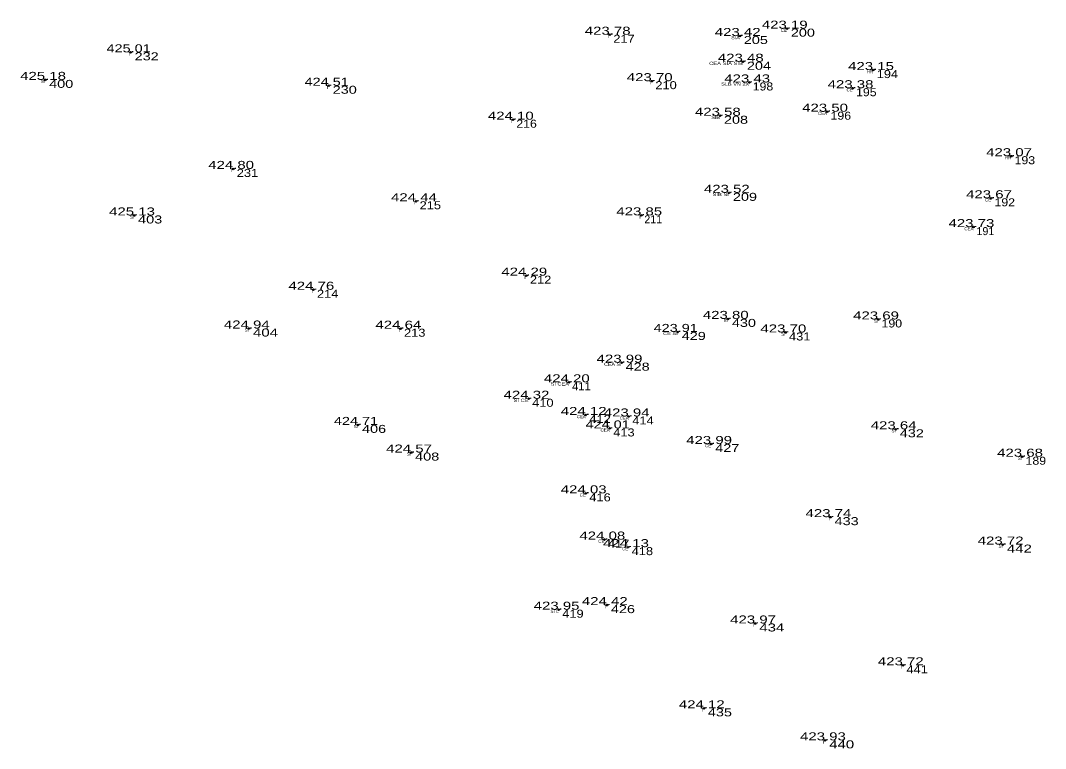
# Model space of a CAD drawing. Extents: x -639373 to -639056, y -1138651 to -1138359.
# Drawn here: x -639278.4 to -639182.3, y -1138568.9 to -1138500.7 of the extents above; entities that cross this region are included whole.
import ezdxf
from ezdxf.enums import TextEntityAlignment as Align

# ---------------------------------------------------------------- set-up
doc = ezdxf.new("R2010")
doc.units = 0
doc.header["$LTSCALE"] = 0.3
doc.header["$PDMODE"] = 32
doc.header["$PDSIZE"] = 0.15
for name, color, linetype in [('11', 7, 'Continuous'), ('13', 7, 'Continuous'), ('14', 7, 'Continuous'), ('57', 7, 'Continuous')]:
    doc.layers.add(name, color=color, linetype=linetype)

msp = doc.modelspace()

# ---------------------------------------------------------------- linework, layer by layer
at = {"layer": '11'}
for p in [(-639223.19, -1138502.05), (-639211, -1138502.17), (-639206.59, -1138501.48), (-639268.11, -1138503.7), (-639210.71, -1138504.58), (-639198.5, -1138505.36), (-639276.12, -1138506.28), (-639249.54, -1138506.83), (-639219.25, -1138506.4), (-639210.11, -1138506.52), (-639200.42, -1138507.06), (-639232.27, -1138510.01), (-639212.86, -1138509.64), (-639202.81, -1138509.26), (-639185.56, -1138513.43), (-639258.49, -1138514.62), (-639241.35, -1138517.65), (-639212.02, -1138516.86), (-639187.44, -1138517.37), (-639267.78, -1138518.98), (-639220.23, -1138518.97), (-639189.09, -1138520.07), (-639231.01, -1138524.62), (-639250.97, -1138525.94), (-639212.12, -1138528.67), (-639198.03, -1138528.72), (-639257.02, -1138529.57), (-639242.81, -1138529.59), (-639216.82, -1138529.89), (-639206.72, -1138529.94), (-639222.08, -1138532.77), (-639227.02, -1138534.61), (-639230.8, -1138536.15), (-639225.44, -1138537.67), (-639221.41, -1138537.81), (-639246.79, -1138538.6), (-639223.2, -1138538.93), (-639196.38, -1138539.01), (-639213.68, -1138540.39), (-639241.81, -1138541.19), (-639184.53, -1138541.58), (-639225.44, -1138545.01), (-639202.49, -1138547.24), (-639223.69, -1138549.34), (-639221.47, -1138550.05), (-639186.35, -1138549.81), (-639227.98, -1138555.91), (-639223.46, -1138555.48), (-639209.56, -1138557.2), (-639195.71, -1138561.12), (-639214.37, -1138565.15), (-639203.01, -1138568.15)]:
    msp.add_point(p, dxfattribs=at)

# ---------------------------------------------------------------- texts
at = {"layer": '13'}
for s, width, p in [(' 217', 1.2, (-639223.19, -1138502.8)), (' 205', 1.35, (-639211, -1138502.92)), (' 200', 1.35, (-639206.59, -1138502.23)), (' 232', 1.35, (-639268.11, -1138504.45)), (' 204', 1.35, (-639210.71, -1138505.33)), (' 194', 1.2, (-639198.5, -1138506.11)), (' 400', 1.35, (-639276.12, -1138507.03)), (' 230', 1.35, (-639249.54, -1138507.58)), (' 210', 1.2, (-639219.25, -1138507.15)), (' 198', 1.15, (-639210.11, -1138507.27)), (' 195', 1.15, (-639200.42, -1138507.81)), (' 216', 1.15, (-639232.27, -1138510.76)), (' 208', 1.35, (-639212.86, -1138510.39)), (' 196', 1.15, (-639202.81, -1138510.01)), (' 193', 1.15, (-639185.56, -1138514.18)), (' 231', 1.2, (-639258.49, -1138515.37)), (' 215', 1.2, (-639241.35, -1138518.4)), (' 209', 1.35, (-639212.02, -1138517.61)), (' 192', 1.15, (-639187.44, -1138518.12)), (' 403', 1.35, (-639267.78, -1138519.73)), (' 212', 1.2, (-639231.01, -1138525.37)), (' 214', 1.2, (-639250.97, -1138526.69)), (' 430', 1.35, (-639212.12, -1138529.42)), (' 190', 1.15, (-639198.03, -1138529.47)), (' 404', 1.4, (-639257.02, -1138530.32)), (' 213', 1.2, (-639242.81, -1138530.34)), (' 429', 1.35, (-639216.82, -1138530.64)), (' 431', 1.2, (-639206.72, -1138530.69)), (' 428', 1.35, (-639222.08, -1138533.52)), (' 411', 1.05, (-639227.02, -1138535.36)), (' 410', 1.2, (-639230.8, -1138536.9)), (' 412', 1.2, (-639225.44, -1138538.42)), (' 414', 1.2, (-639221.41, -1138538.56)), (' 406', 1.35, (-639246.79, -1138539.35)), (' 413', 1.2, (-639223.2, -1138539.68)), (' 432', 1.35, (-639196.38, -1138539.76)), (' 427', 1.35, (-639213.68, -1138541.14)), (' 408', 1.35, (-639241.81, -1138541.94)), (' 189', 1.15, (-639184.53, -1138542.33)), (' 416', 1.2, (-639225.44, -1138545.76)), (' 433', 1.35, (-639202.49, -1138547.99)), (' 417', 1.2, (-639223.69, -1138550.09)), (' 418', 1.2, (-639221.47, -1138550.8)), (' 442', 1.4, (-639186.35, -1138550.56)), (' 419', 1.2, (-639227.98, -1138556.66)), (' 426', 1.35, (-639223.46, -1138556.23)), (' 434', 1.4, (-639209.56, -1138557.95)), (' 441', 1.2, (-639195.71, -1138561.87)), (' 435', 1.35, (-639214.37, -1138565.9)), (' 440', 1.4, (-639203.01, -1138568.9))]:
    msp.add_text(s, height=0.75, dxfattribs=dict(at, width=width)).set_placement(p)
for s, p in [(' 211', (-639220.23, -1138519.72)), (' 191', (-639189.09, -1138520.82))]:
    msp.add_text(s, height=0.75, dxfattribs=at).set_placement(p)
at = {"layer": '14'}
for s, width, p in [('423.78 ', 1.4, (-639223.19, -1138502.05)), ('423.19 ', 1.4, (-639206.59, -1138501.48)), ('423.42 ', 1.4, (-639211, -1138502.17)), ('425.01 ', 1.35, (-639268.109, -1138503.7)), ('423.48 ', 1.4, (-639210.71, -1138504.58)), ('423.15 ', 1.4, (-639198.5, -1138505.36)), ('425.18 ', 1.4, (-639276.12, -1138506.28)), ('424.51 ', 1.35, (-639249.539, -1138506.83)), ('423.70 ', 1.4, (-639219.25, -1138506.4)), ('423.43 ', 1.4, (-639210.11, -1138506.52)), ('423.38 ', 1.4, (-639200.42, -1138507.06)), ('423.58 ', 1.4, (-639212.86, -1138509.64)), ('423.50 ', 1.4, (-639202.81, -1138509.26)), ('424.10 ', 1.4, (-639232.27, -1138510.01)), ('423.07 ', 1.4, (-639185.56, -1138513.43)), ('424.80 ', 1.4, (-639258.49, -1138514.62)), ('423.52 ', 1.4, (-639212.02, -1138516.86)), ('423.67 ', 1.4, (-639187.44, -1138517.37)), ('424.44 ', 1.4, (-639241.35, -1138517.65)), ('425.13 ', 1.4, (-639267.78, -1138518.98)), ('423.85 ', 1.4, (-639220.23, -1138518.97)), ('423.73 ', 1.4, (-639189.09, -1138520.07)), ('424.29 ', 1.4, (-639231.01, -1138524.62)), ('424.76 ', 1.4, (-639250.969, -1138525.94)), ('423.80 ', 1.4, (-639212.12, -1138528.67)), ('423.69 ', 1.4, (-639198.03, -1138528.72)), ('424.94 ', 1.4, (-639257.02, -1138529.57)), ('424.64 ', 1.4, (-639242.81, -1138529.59)), ('423.91 ', 1.35, (-639216.819, -1138529.89)), ('423.70 ', 1.4, (-639206.72, -1138529.94)), ('423.99 ', 1.4, (-639222.08, -1138532.77)), ('424.20 ', 1.4, (-639227.02, -1138534.61)), ('424.32 ', 1.4, (-639230.8, -1138536.15)), ('424.12 ', 1.4, (-639225.44, -1138537.67)), ('424.71 ', 1.35, (-639246.789, -1138538.6)), ('423.94 ', 1.4, (-639221.41, -1138537.81)), ('424.01 ', 1.35, (-639223.199, -1138538.93)), ('423.64 ', 1.4, (-639196.38, -1138539.01)), ('423.99 ', 1.4, (-639213.68, -1138540.39)), ('424.57 ', 1.4, (-639241.81, -1138541.19)), ('423.68 ', 1.4, (-639184.53, -1138541.58)), ('424.03 ', 1.4, (-639225.44, -1138545.01)), ('423.74 ', 1.4, (-639202.49, -1138547.24)), ('424.08 ', 1.4, (-639223.69, -1138549.34)), ('424.13 ', 1.4, (-639221.47, -1138550.05)), ('423.72 ', 1.4, (-639186.35, -1138549.81)), ('423.95 ', 1.4, (-639227.98, -1138555.91)), ('424.42 ', 1.4, (-639223.46, -1138555.48)), ('423.97 ', 1.4, (-639209.56, -1138557.2)), ('423.72 ', 1.4, (-639195.71, -1138561.12)), ('424.12 ', 1.4, (-639214.37, -1138565.15)), ('423.93 ', 1.4, (-639203.01, -1138568.15))]:
    msp.add_text(s, height=0.75, dxfattribs=dict(at, width=width)).set_placement(p, align=Align.CENTER)
at = {"layer": '57'}
for s, width, p in [('T', 0.85, (-639223.19, -1138502.35)), ('SIA', 1.25, (-639211, -1138502.47)), ('CE', 0.9, (-639206.59, -1138501.78)), ('T', 0.85, (-639268.11, -1138504)), ('CEA SIA SIB', 1.35, (-639210.709, -1138504.88)), ('HR', 0.85, (-639198.499, -1138505.66)), ('SI', 1.05, (-639276.12, -1138506.58)), ('T', 0.85, (-639249.54, -1138507.13)), ('T', 0.85, (-639219.25, -1138506.7)), ('SLB VN 2X', 1.3, (-639210.11, -1138506.82)), ('CE', 0.9, (-639200.42, -1138507.36)), ('SIB', 1.25, (-639212.859, -1138509.94)), ('T', 0.85, (-639232.27, -1138510.31)), ('HR', 0.85, (-639185.559, -1138513.73)), ('T', 0.85, (-639258.49, -1138514.92)), ('T', 0.85, (-639241.35, -1138517.95)), ('SIB SI', 1.35, (-639212.02, -1138517.16)), ('CE', 0.9, (-639187.44, -1138517.67)), ('SI', 1.05, (-639267.78, -1138519.28)), ('T', 0.85, (-639220.23, -1138519.27)), ('T', 0.85, (-639231.01, -1138524.92)), ('T', 0.85, (-639250.97, -1138526.24)), ('SI', 1.05, (-639212.12, -1138528.97)), ('SI', 1.05, (-639198.03, -1138529.02)), ('SI', 1.05, (-639257.02, -1138529.87)), ('T', 0.85, (-639242.81, -1138529.89)), ('CE SI', 1.3, (-639216.82, -1138530.19)), ('SI', 1.05, (-639206.72, -1138530.24)), ('CEA SI', 1.25, (-639222.08, -1138533.07)), ('SI CEA', 1.3, (-639227.02, -1138534.91)), ('SI CE', 1.35, (-639230.8, -1138536.45)), ('SI', 1.05, (-639246.79, -1138538.9)), ('SI', 1.05, (-639196.38, -1138539.31)), ('CE', 0.9, (-639213.68, -1138540.69)), ('SI', 1.05, (-639241.81, -1138541.49)), ('SI', 1.05, (-639184.53, -1138541.88)), ('CE', 0.9, (-639225.44, -1138545.31)), ('T', 0.85, (-639202.49, -1138547.54)), ('CE', 0.9, (-639223.69, -1138549.64)), ('CE', 0.9, (-639221.47, -1138550.35)), ('SI', 1.05, (-639186.35, -1138550.11)), ('STL', 1.05, (-639227.979, -1138556.21)), ('T', 0.85, (-639223.46, -1138555.78)), ('T', 0.85, (-639209.56, -1138557.5)), ('T', 0.85, (-639195.71, -1138561.42)), ('T', 0.85, (-639214.37, -1138565.45)), ('T', 0.85, (-639203.01, -1138568.45))]:
    msp.add_text(s, height=0.3, dxfattribs=dict(at, width=width)).set_placement(p, align=Align.RIGHT)
for p in [(-639202.81, -1138509.56), (-639189.09, -1138520.37), (-639225.44, -1138537.97), (-639221.41, -1138538.11), (-639223.2, -1138539.23)]:
    msp.add_text('CEA', height=0.3, dxfattribs=at).set_placement(p, align=Align.RIGHT)

doc.saveas('drawing.dxf')
